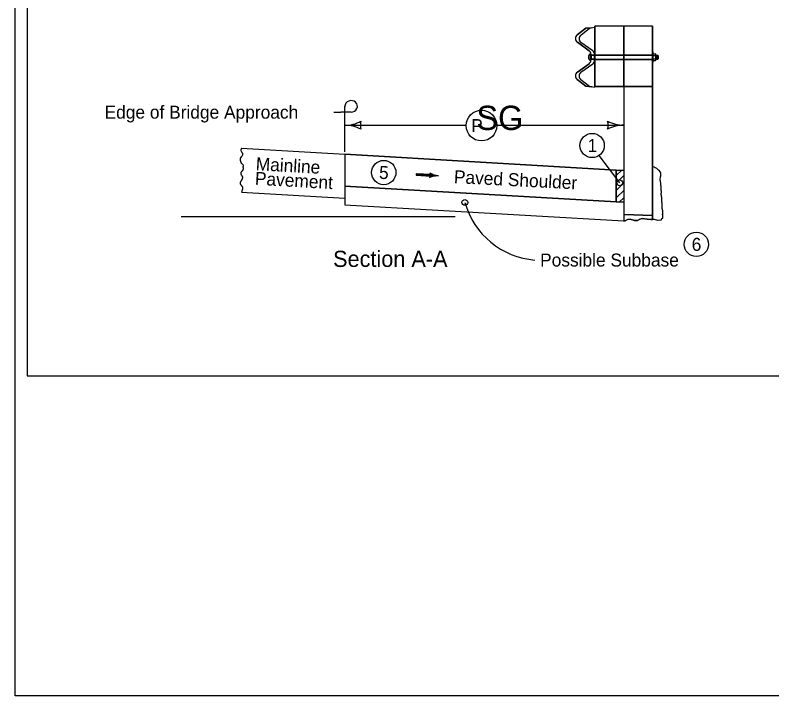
# Model space of a CAD drawing. Extents: x 9538 to 81668, y 7600 to 11751.
# Drawn here: x 13733 to 14667, y 7924 to 8764 of the extents above; entities that cross this region are included whole.
import ezdxf

# ---------------------------------------------------------------- set-up
doc = ezdxf.new("R2010")
doc.units = 0
for name, color, linetype in [('Default', 7, 'Continuous'), ('DsnShtMinorGrid13', 7, 'Continuous'), ('DsnShtMinorGrid14', 7, 'Continuous'), ('dsnStdCells', 7, 'Continuous'), ('dsnStdDimension', 7, 'Continuous'), ('dsnStdNameDate', 7, 'Continuous'), ('dsnStdNote', 7, 'Continuous'), ('dsnStdShading', 7, 'Continuous'), ('dsnStdTable', 7, 'Continuous')]:
    doc.layers.add(name, color=color, linetype=linetype)

msp = doc.modelspace()

# ---------------------------------------------------------------- linework, layer by layer
at = {"layer": 'Default'}
msp.add_lwpolyline([(13732.53, 9944.02), (16867.53, 9944.02), (16867.53, 7924.02), (13732.53, 7924.02)], close=True, dxfattribs=at)
at = {"layer": 'DsnShtMinorGrid13'}
for centre, radius in [((14444.79, 8603.28), 15), ((14187.58, 8569.91), 15), ((14478.92, 8557.17), 3.58), ((14573.38, 8481.26), 15)]:
    msp.add_circle(centre, radius, dxfattribs=at)
at = {"layer": 'DsnShtMinorGrid14'}
msp.add_circle((14287.62, 8533.07), 3.54, dxfattribs=at)
at = {"layer": 'dsnStdCells'}
for p, q in [((14426.56, 8730.73), (14441.07, 8720.31)), ((14441.07, 8704.24), (14426.56, 8693.82))]:
    msp.add_line(p, q, dxfattribs=at)
for points in [[(14430.81, 8739.63), (14430.8, 8739.62), (14441.57, 8748.02), (14443.46, 8748.36), (14437.13, 8748.24), (14426.37, 8739.85)], [(14483.85, 8714.93), (14483.85, 8750.61), (14448.31, 8750.61), (14448.31, 8714.93), (14448.31, 8714.93), (14483.85, 8714.93)], [(14519.4, 8714.93), (14519.4, 8718.93), (14519.4, 8750.61), (14483.85, 8750.61), (14483.85, 8714.93), (14519.4, 8714.93)], [(14445.51, 8720.09), (14445.54, 8720.07), (14430.98, 8730.53), (14431.01, 8730.51)], [(14443.46, 8715.68), (14443.46, 8714.6), (14447.91, 8714.6), (14447.91, 8715.46), (14447.91, 8715.46)], [(14447.91, 8708.65), (14447.91, 8708.65), (14447.91, 8709.93), (14443.47, 8709.93), (14443.47, 8708.87), (14443.47, 8709.93), (14443.46, 8709.93), (14443.46, 8708.87)], [(14448.31, 8714.6), (14448.31, 8709.93), (14448.31, 8709.93), (14483.85, 8709.93), (14483.85, 8714.6), (14448.31, 8714.6), (14448.31, 8714.6)], [(14448.31, 8709.6), (14448.31, 8675.96), (14483.85, 8675.96), (14483.85, 8709.6), (14448.31, 8709.6)], [(14519.4, 8709.93), (14519.4, 8714.6), (14483.85, 8714.6), (14483.85, 8709.93), (14519.4, 8709.93)], [(14519.4, 8675.96), (14519.4, 8705.6), (14519.4, 8709.6), (14483.85, 8709.6), (14483.85, 8675.96), (14519.4, 8675.96)], [(14431.01, 8693.6), (14430.98, 8693.58), (14445.54, 8704.04), (14445.51, 8704.02)], [(14426.37, 8684.7), (14437.13, 8676.31), (14444.23, 8675.62), (14441.57, 8676.09), (14430.8, 8684.5), (14430.81, 8684.48)], [(14519.4, 8517.01), (14519.4, 8675.96), (14483.85, 8675.96), (14483.85, 8572.99), (14483.85, 8566.3), (14483.85, 8566.3), (14483.85, 8566.3), (14483.85, 8557.07), (14483.85, 8557.07), (14483.85, 8557.07), (14483.85, 8547.93), (14483.85, 8547.93), (14483.85, 8547.93), (14483.85, 8541), (14483.85, 8518.17), (14519.4, 8517.01)], [(14519.4, 8517.01), (14483.85, 8518.17), (14483.85, 8510.15), (14485.49, 8510.38), (14488.25, 8511.97), (14491.53, 8512.5), (14497.15, 8510.91), (14500.86, 8510.69), (14503.51, 8512.5), (14506.58, 8513.13), (14512.84, 8512.39), (14517.08, 8511.97), (14519.4, 8511.97), (14519.4, 8517.01)]]:
    msp.add_lwpolyline(points, dxfattribs=at)
msp.add_lwpolyline([(14447.91, 8714.6), (14443.46, 8714.6), (14443.47, 8711.14), (14443.47, 8712.27), (14443.47, 8709.93), (14447.91, 8709.93)], close=True, dxfattribs=at)
for centre, start, end in [((14429.84, 8735.36), 127.75002, 234.69086), ((14434.29, 8735.14), 127.75002, 234.69086), ((14437.79, 8715.68), 0, 54.69099), ((14442.23, 8715.46), 0, 54.69099), ((14437.79, 8708.87), 305.30901, 0), ((14442.23, 8708.65), 305.30901, 0), ((14429.84, 8689.19), 125.30914, 232.24998), ((14434.29, 8688.97), 125.30914, 232.24998)]:
    msp.add_arc(centre, 5.68, start, end, dxfattribs=at)
at = {"layer": 'dsnStdDimension'}
for p, q in [((14139.46, 8628.24), (14289.29, 8628.24)), ((14327.15, 8628.4), (14483.85, 8628.4))]:
    msp.add_line(p, q, dxfattribs=at)
msp.add_circle((14308.22, 8627.84), 18.93, dxfattribs=at)
for centre, radius, start, end in [((14139.46, 8670.74), 42.5, 270, 298.07249), ((14175.1, 8628.24), 16.42, 162.26665, 197.73335), ((14448.22, 8628.4), 16.42, 342.26665, 17.73335), ((14483.85, 8670.9), 42.5, 241.92751, 270), ((14139.46, 8585.74), 42.5, 61.92751, 90), ((14483.85, 8585.9), 42.5, 90, 118.07249), ((14381.78, 8559.36), 97.76, 195.59781, 265.55799)]:
    msp.add_arc(centre, radius, start, end, dxfattribs=at)
at = {"layer": 'dsnStdNameDate'}
msp.add_line((14478.92, 8557.17), (14453.53, 8591.09), dxfattribs=at)
at = {"layer": 'dsnStdNote'}
for p, q in [((14139.46, 8631.56), (14139.46, 8652.42)), ((14126.09, 8644.41), (14134.78, 8644.41)), ((14147.27, 8644.41), (14134.78, 8644.41)), ((14139.46, 8595.62), (14139.46, 8631.56)), ((14245.85, 8566.52), (14227.64, 8567.57)), ((14245.86, 8567.53), (14245.86, 8567.53)), ((14245.74, 8565.58), (14245.74, 8565.58))]:
    msp.add_line(p, q, dxfattribs=at)
for points in [[(14245.87, 8567.46), (14227.71, 8568.51), (14227.58, 8566.63), (14245.74, 8565.58), (14245.8, 8567.19), (14227.93, 8568.29), (14227.87, 8566.79), (14245.36, 8565.84), (14245.48, 8566.96), (14228.16, 8568.02), (14228.14, 8567.02), (14245.15, 8566.04), (14245.24, 8566.75), (14228.35, 8567.8), (14228.33, 8567.24), (14244.94, 8566.31)], [(14245.47, 8568.72), (14246.16, 8567.55), (14246.14, 8565.9), (14245.38, 8564.51), (14248.14, 8565.37), (14251.33, 8566.02), (14252.23, 8566.16), (14249.99, 8566.7), (14246.76, 8567.93), (14245.82, 8568.47), (14245.94, 8564.95), (14250.89, 8566.17), (14246.25, 8567.75), (14246.26, 8565.33), (14249.66, 8566.26), (14246.66, 8567.12), (14246.43, 8565.74), (14248.59, 8566.24), (14247, 8566.75), (14246.86, 8566.09), (14247.65, 8566.25)]]:
    msp.add_lwpolyline(points, dxfattribs=at)
for centre, major_axis, start_param, end_param in [((14147.27, 8651.54), (-7.81, 0), 1.570796, 6.283185), ((14242.08, 8566.74), (3.88, 0), 5.202895, 7.237436), ((14254.35, 8545.74), (22.17, 0), 1.537172, 2.061295), ((14257.14, 8586.16), (-22.17, 0), 0.954258, 1.478381)]:
    msp.add_ellipse(centre, major_axis=major_axis, ratio=0.913811, start_param=start_param, end_param=end_param, dxfattribs=at)
at = {"layer": 'dsnStdShading'}
for p, q in [((13747.53, 9929.02), (13747.53, 8319.02)), ((13747.53, 8319.02), (16843.22, 8319.02))]:
    msp.add_line(p, q, dxfattribs=at)
at = {"layer": 'dsnStdTable'}
for p, q in [((14426.37, 8739.85), (14437.13, 8748.24)), ((14430.8, 8739.62), (14441.57, 8748.02)), ((14437.13, 8748.24), (14443.46, 8748.36)), ((14441.57, 8748.02), (14447.91, 8749.14)), ((14519.4, 8750.61), (14448.31, 8750.61)), ((14448.31, 8675.96), (14448.31, 8750.61)), ((14483.85, 8675.96), (14483.85, 8750.61)), ((14519.4, 8750.61), (14519.4, 8511.97)), ((14441.07, 8720.31), (14426.56, 8730.73)), ((14445.54, 8720.07), (14430.98, 8730.53)), ((14442.69, 8708.21), (14442.69, 8716.29)), ((14443.47, 8708.87), (14443.46, 8715.68)), ((14447.91, 8712.06), (14447.91, 8715.46)), ((14519.4, 8718.9), (14520.08, 8718.9)), ((14520.08, 8705.57), (14520.08, 8718.9)), ((14520.08, 8716.28), (14523.05, 8716.28)), ((14442.69, 8714.6), (14448.12, 8714.6)), ((14442.69, 8709.93), (14448.31, 8709.93)), ((14443.46, 8708.87), (14443.47, 8712.27)), ((14443.47, 8712.27), (14443.47, 8708.87)), ((14443.64, 8714.6), (14448.31, 8714.6)), ((14447.91, 8708.65), (14447.91, 8712.06)), ((14447.91, 8712.06), (14447.91, 8708.65)), ((14448.3, 8709.6), (14519.4, 8709.6)), ((14448.31, 8714.93), (14519.4, 8714.93)), ((14448.31, 8714.6), (14519.4, 8714.6)), ((14448.31, 8709.93), (14519.4, 8709.93)), ((14520.08, 8714.26), (14523.05, 8714.26)), ((14520.08, 8710.22), (14523.05, 8710.22)), ((14520.08, 8708.2), (14523.05, 8708.2)), ((14523.41, 8709.21), (14523.41, 8715.27)), ((14523.41, 8714.57), (14525.78, 8714.57)), ((14523.41, 8709.9), (14525.78, 8709.9)), ((14524.3, 8714.57), (14524.3, 8709.9)), ((14525.04, 8714.57), (14525.04, 8709.9)), ((14525.78, 8714.57), (14526.23, 8714.04)), ((14525.78, 8714.57), (14525.78, 8709.9)), ((14526.23, 8710.44), (14525.78, 8709.9)), ((14526.23, 8714.04), (14526.23, 8710.44)), ((14426.56, 8693.82), (14441.07, 8704.24)), ((14430.98, 8693.58), (14445.54, 8704.04)), ((14519.4, 8705.57), (14520.08, 8705.57)), ((14437.13, 8676.31), (14426.37, 8684.7)), ((14441.57, 8676.09), (14430.8, 8684.5)), ((14444.23, 8675.62), (14437.13, 8676.31)), ((14447.91, 8674.97), (14441.57, 8676.09)), ((14483.85, 8675.96), (14448.31, 8675.96)), ((14483.85, 8675.96), (14483.85, 8509.43)), ((14011.85, 8599.9), (14139.46, 8592.48)), ((14139.46, 8592.48), (14139.46, 8538.47)), ((14139.46, 8592.48), (14474.6, 8572.99)), ((14474.6, 8572.99), (14139.46, 8592.48)), ((14139.46, 8592.48), (14139.46, 8552.88)), ((14474.6, 8566.25), (14481.34, 8572.99)), ((14474.6, 8566.25), (14481.34, 8572.99)), ((14474.6, 8566.25), (14481.34, 8572.99)), ((14474.6, 8566.25), (14481.34, 8572.99)), ((14474.6, 8572.99), (14483.84, 8572.99)), ((14474.6, 8572.99), (14474.6, 8533.56)), ((14474.6, 8533.56), (14474.6, 8572.99)), ((14474.6, 8557.06), (14483.84, 8566.3)), ((14474.6, 8557.06), (14483.84, 8566.3)), ((14474.6, 8557.06), (14483.84, 8566.3)), ((14474.6, 8557.06), (14483.84, 8566.3)), ((14529.45, 8566.23), (14529.45, 8566.23)), ((14474.6, 8547.84), (14483.84, 8557.07)), ((14474.6, 8547.84), (14483.84, 8557.07)), ((14474.6, 8547.84), (14483.84, 8557.07)), ((14474.6, 8547.84), (14483.84, 8557.07)), ((14474.6, 8533.56), (14139.46, 8552.88)), ((14139.46, 8552.88), (14474.6, 8533.56)), ((14474.6, 8538.61), (14483.84, 8547.84)), ((14012.03, 8545.88), (14139.46, 8538.47)), ((14139.46, 8538.47), (14139.46, 8530.05)), ((14478.7, 8533.56), (14483.84, 8538.7)), ((14139.46, 8530.05), (14483.85, 8510.19)), ((14474.6, 8533.56), (14483.84, 8533.56)), ((13937.41, 8515.64), (14275.91, 8515.64)), ((14529.8, 8507.16), (14529.8, 8507.16))]:
    msp.add_line(p, q, dxfattribs=at)
for points in [[(14523.4, 8709.53), (14523.35, 8709.8), (14523.31, 8709.97), (14523.22, 8710.13), (14523.1, 8710.22), (14523.18, 8710.32), (14523.26, 8710.54), (14523.32, 8710.85), (14523.4, 8711.6), (14523.4, 8709.53), (14523.38, 8709.67), (14523.34, 8709.88), (14523.26, 8710.09), (14523.14, 8710.21), (14523.18, 8710.29), (14523.24, 8710.44), (14523.34, 8710.94), (14523.38, 8711.32), (14523.38, 8709.72), (14523.35, 8709.84), (14523.31, 8710), (14523.18, 8710.21), (14523.23, 8710.38), (14523.31, 8710.71), (14523.37, 8711.04), (14523.36, 8709.87), (14523.32, 8710), (14523.21, 8710.2), (14523.25, 8710.41), (14523.31, 8710.67), (14523.34, 8710.84), (14523.34, 8709.98), (14523.28, 8710.09), (14523.23, 8710.2), (14523.32, 8710.66), (14523.32, 8710.06), (14523.25, 8710.2), (14523.3, 8710.49), (14523.3, 8710.14), (14523.27, 8710.21), (14523.28, 8710.31), (14523.28, 8710.23)], [(14523.11, 8714.26), (14523.18, 8714.3), (14523.26, 8714.41), (14523.34, 8714.63), (14523.4, 8714.91), (14523.4, 8712.97), (14523.34, 8713.48), (14523.29, 8713.85), (14523.17, 8714.17), (14523.11, 8714.26), (14523.17, 8714.27), (14523.27, 8714.41), (14523.36, 8714.64), (14523.38, 8714.79), (14523.38, 8713.26), (14523.31, 8713.75), (14523.25, 8714.01), (14523.15, 8714.24), (14523.18, 8714.25), (14523.32, 8714.47), (14523.36, 8714.62), (14523.36, 8713.51), (14523.17, 8714.23), (14523.34, 8714.5), (14523.34, 8713.65), (14523.2, 8714.21), (14523.32, 8714.43), (14523.33, 8713.79), (14523.22, 8714.2), (14523.31, 8714.37), (14523.31, 8713.96), (14523.24, 8714.18), (14523.29, 8714.3), (14523.29, 8714.09), (14523.26, 8714.17), (14523.27, 8714.21)], [(14529.92, 8542.38), (14529.86, 8542.11), (14529.86, 8541.92), (14529.86, 8541.72), (14529.86, 8541.53), (14529.86, 8541.33), (14529.86, 8541.14), (14529.86, 8540.84), (14529.86, 8540.65), (14529.96, 8540.35), (14530.06, 8540.06), (14530.25, 8539.87), (14530.25, 8539.67), (14530.35, 8539.47), (14530.35, 8539.28), (14530.35, 8539.08), (14530.45, 8538.99), (14530.45, 8538.79), (14530.45, 8538.59), (14530.45, 8538.4), (14530.45, 8538.2), (14530.45, 8538.01), (14530.45, 8537.72), (14530.45, 8537.42), (14530.45, 8537.23), (14530.45, 8536.93), (14530.45, 8536.74), (14530.45, 8536.54), (14530.55, 8536.45), (14530.55, 8536.25), (14530.55, 8536.05), (14530.55, 8535.86), (14530.55, 8535.66), (14530.55, 8535.47), (14530.55, 8535.27), (14530.55, 8535.08), (14530.55, 8534.88), (14530.55, 8534.69), (14530.55, 8534.49), (14530.55, 8534.3), (14530.55, 8534.1), (14530.55, 8533.91), (14530.55, 8533.71), (14530.55, 8533.51), (14530.55, 8533.32), (14530.55, 8533.12), (14530.55, 8532.93), (14530.64, 8532.83), (14530.64, 8532.63), (14530.64, 8532.44), (14530.74, 8532.34), (14530.74, 8532.15), (14530.74, 8531.95), (14530.84, 8531.85), (14530.84, 8531.66), (14530.84, 8531.46), (14530.84, 8531.27), (14530.84, 8530.97), (14530.94, 8530.68), (14530.94, 8530.49), (14530.94, 8530.29), (14530.94, 8530.09), (14530.94, 8529.9), (14530.94, 8529.7), (14530.94, 8529.51), (14530.94, 8529.31), (14530.94, 8529.12), (14530.94, 8528.92), (14530.94, 8528.73), (14530.94, 8528.53), (14530.94, 8528.34), (14530.94, 8528.14), (14530.94, 8527.95), (14530.94, 8527.75), (14530.94, 8527.55), (14530.94, 8527.36), (14530.94, 8527.16), (14530.94, 8526.97), (14530.94, 8526.77), (14530.94, 8526.58), (14530.94, 8526.38), (14530.94, 8526.19), (14530.94, 8525.99), (14530.94, 8525.8), (14530.94, 8525.6), (14530.94, 8525.4), (14530.94, 8525.21), (14530.94, 8525.01), (14531.03, 8524.92), (14531.03, 8524.62), (14531.03, 8524.43), (14531.13, 8524.23), (14531.23, 8523.94), (14531.23, 8523.74), (14531.33, 8523.65), (14531.33, 8523.45), (14531.42, 8523.35), (14531.52, 8523.26), (14531.52, 8523.06), (14531.52, 8522.86), (14531.52, 8522.67), (14531.62, 8522.57), (14531.62, 8522.38), (14531.62, 8522.18), (14531.62, 8521.99), (14531.62, 8521.79), (14531.62, 8521.59), (14531.62, 8521.4), (14531.62, 8521.2), (14531.62, 8521.01), (14531.62, 8520.81), (14531.62, 8520.62), (14531.62, 8520.42), (14531.62, 8520.23), (14531.62, 8520.03), (14531.62, 8519.84), (14531.62, 8519.64), (14531.62, 8519.44), (14531.62, 8519.25), (14531.62, 8519.05), (14531.62, 8518.86), (14531.62, 8518.66), (14531.62, 8518.47), (14531.62, 8518.27), (14531.62, 8518.08), (14531.62, 8517.88), (14531.62, 8517.69), (14531.62, 8517.69), (14531.62, 8517.98), (14531.62, 8518.17), (14531.62, 8518.37), (14531.62, 8518.17), (14531.62, 8517.98), (14531.62, 8517.78), (14531.62, 8517.59), (14531.62, 8517.39), (14531.62, 8517.2), (14531.62, 8517), (14531.62, 8516.81), (14531.62, 8516.61), (14531.62, 8516.42), (14531.62, 8516.22), (14531.62, 8516.03), (14531.62, 8515.83), (14531.62, 8515.63), (14531.62, 8515.44), (14531.52, 8515.34), (14531.52, 8515.15), (14531.52, 8514.95), (14531.52, 8514.76), (14531.52, 8514.56), (14531.52, 8514.36), (14531.52, 8514.17), (14531.52, 8513.97), (14531.52, 8513.78), (14531.52, 8513.58), (14531.52, 8513.39), (14531.42, 8513.29), (14531.33, 8513.09), (14531.23, 8513), (14531.13, 8512.9), (14531.03, 8512.8), (14530.84, 8512.7), (14530.64, 8512.7), (14530.55, 8512.61), (14530.45, 8512.51), (14530.35, 8512.41), (14530.15, 8512.31), (14530.06, 8512.21), (14530.06, 8512.02), (14529.96, 8511.92), (14529.96, 8511.73), (14529.96, 8511.53), (14529.96, 8511.34), (14529.96, 8511.14), (14529.96, 8511.04), (14529.96, 8511.24)], [(14529.92, 8510.92), (14525.77, 8510.8), (14521.63, 8511.97), (14517.08, 8511.97), (14512.84, 8512.39), (14506.58, 8513.13), (14503.51, 8512.5), (14500.86, 8510.69), (14497.15, 8510.91), (14491.53, 8512.5), (14488.25, 8511.97), (14485.49, 8510.38), (14483.85, 8510.15)]]:
    msp.add_lwpolyline(points, dxfattribs=at)
msp.add_circle((14187.58, 8569.91), 15, dxfattribs=at)
for centre, radius, start, end in [((14429.84, 8735.36), 5.68, 127.75002, 234.69086), ((14434.29, 8735.14), 5.68, 127.75002, 234.69086), ((14444.77, 8712.26), 4.54, 117.20289, 242.8461), ((14437.79, 8715.68), 5.68, 360, 54.69099), ((14442.23, 8715.46), 5.68, 360, 54.69099), ((14437.79, 8708.87), 5.68, 305.30901, 0), ((14442.23, 8708.65), 5.68, 305.30901, 0), ((14429.84, 8689.19), 5.68, 125.30914, 232.24998), ((14434.29, 8688.97), 5.68, 125.30914, 232.24998)]:
    msp.add_arc(centre, radius, start, end, dxfattribs=at)
for centre in [(14523.05, 8715.27), (14523.05, 8709.21)]:
    msp.add_ellipse(centre, major_axis=(0, -1.01), ratio=0.362258, start_param=6.283156, end_param=9.424748, dxfattribs=at)
for points in [[(14011.85, 8599.9), (14011.34, 8596.3), (14012.38, 8594.79), (14013.25, 8592.5), (14012.64, 8590.44), (14010.74, 8588.06), (14010.22, 8586.16), (14010.74, 8583.87), (14011.6, 8581.49), (14012.64, 8580.78), (14014.03, 8578.24), (14014.02, 8577.4)], [(14012.06, 8560.29), (14012.27, 8560.54), (14012.47, 8560.8), (14012.82, 8561.36), (14013.1, 8561.95), (14013.22, 8562.26), (14013.32, 8562.57), (14013.45, 8563.19), (14013.5, 8563.81), (14013.45, 8564.4), (14013.39, 8564.68), (14013.35, 8564.81), (14013.31, 8564.94), (14013.1, 8565.32), (14012.82, 8565.68), (14012.52, 8566.05), (14012.27, 8566.45), (14012.13, 8566.73), (14011.99, 8567.01), (14011.73, 8567.59), (14011.53, 8568.15), (14011.45, 8568.45), (14011.4, 8568.74), (14011.39, 8568.87), (14011.39, 8569), (14011.54, 8569.77), (14011.75, 8570.29), (14012.01, 8570.8), (14012.45, 8571.44), (14012.97, 8571.98), (14013.48, 8572.53), (14013.72, 8572.84), (14013.91, 8573.18), (14014.12, 8573.65), (14014.28, 8574.13), (14014.38, 8574.6), (14014.41, 8574.84), (14014.43, 8574.96), (14014.43, 8575.08), (14014.39, 8575.59), (14014.24, 8576.1), (14014.19, 8576.23), (14014.13, 8576.35), (14014.08, 8576.48), (14014.06, 8576.61), (14014.02, 8577.4)], [(14529.92, 8542.38), (14530.24, 8545.29), (14530.02, 8550.15), (14529.58, 8555.9), (14528.91, 8560.33), (14529.13, 8563.64), (14529.58, 8567.84), (14528.91, 8570.94), (14526.7, 8572.93), (14524.71, 8574.7), (14522.5, 8575.81), (14520.29, 8577.13), (14519.41, 8577.8)], [(14012.06, 8560.29), (14011.84, 8560.06), (14011.6, 8559.82), (14011.36, 8559.58), (14011.18, 8559.31), (14011.04, 8559.03), (14010.9, 8558.74), (14010.64, 8558.17), (14010.53, 8557.89), (14010.43, 8557.6), (14010.36, 8557.31), (14010.33, 8557.16), (14010.31, 8557.01), (14010.32, 8556.5), (14010.45, 8555.98), (14010.66, 8555.46), (14010.92, 8554.95), (14011.36, 8554.32), (14011.88, 8553.77), (14012.4, 8553.22), (14012.63, 8552.92), (14012.83, 8552.58), (14013.23, 8551.63), (14013.34, 8551.16), (14013.35, 8550.68), (14013.31, 8550.39), (14013.26, 8550.1), (14013.21, 8549.81), (14013.14, 8549.53), (14012.83, 8548.38), (14012.65, 8547.77), (14012.45, 8547.17), (14012.23, 8546.58), (14012.1, 8546.29), (14011.96, 8546.01), (14011.88, 8545.89)]]:
    msp.add_spline(points, degree=3, dxfattribs=at)

# ---------------------------------------------------------------- texts
at = {"layer": 'DsnShtMinorGrid13'}
for s, p in [('1', (14439.17, 8595.28)), ('6', (14567.67, 8473.26))]:
    msp.add_text(s, height=16, dxfattribs=at).set_placement(p)
msp.add_text('5', height=16, rotation=356.69973, dxfattribs=at).set_placement((14181.36, 8562.26))
at = {"layer": 'dsnStdDimension'}
for s, height, p in [('SG', 30, (14301.94, 8622.4)), ('P', 16, (14295.51, 8619.84))]:
    msp.add_text(s, height=height, dxfattribs=at).set_placement(p)
at = {"layer": 'dsnStdNote'}
for s, height, p in [('Edge of Bridge Approach', 16, (13842.93, 8636.41)), ('Section A-A', 20, (14125.04, 8453.39)), ('Possible Subbase', 16, (14380.56, 8453.89))]:
    msp.add_text(s, height=height, dxfattribs=at).set_placement(p)
for s, rotation, p in [('Mainline', 356.73462, (14029.22, 8572.86)), ('Pavement', 356.73462, (14028.19, 8554.89)), ('Paved Shoulder ', 357.0678, (14273.86, 8556.89))]:
    msp.add_text(s, height=16, rotation=rotation, dxfattribs=at).set_placement(p)

doc.saveas('drawing.dxf')
